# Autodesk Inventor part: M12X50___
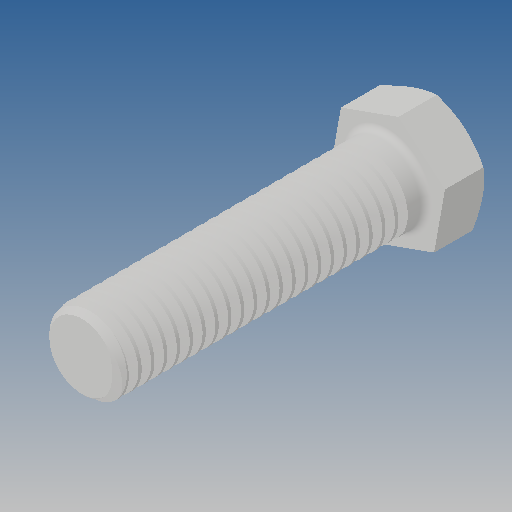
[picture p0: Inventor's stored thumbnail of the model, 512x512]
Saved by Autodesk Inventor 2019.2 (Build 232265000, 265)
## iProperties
Created: 2010-06
Part Number: M12X50___
Material: Ogólny
Document SubType Name: Modeling
Designer: CADENGINEERING4
Density: 1 g/cm^3
Appearance: Domyślna
Author: CADENGINEERING4
Revision Number: ANY
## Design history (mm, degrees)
feature "NONE"
node "Bryła1"
